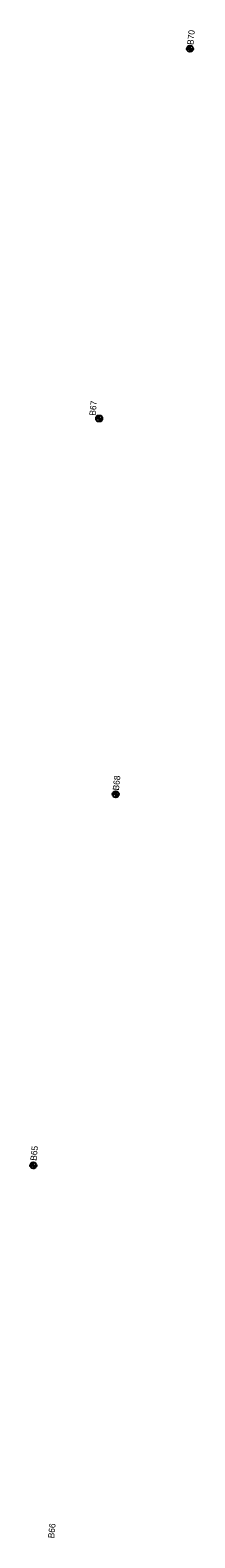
# Model space of a CAD drawing. Extents: x 327762 to 372792, y 127949 to 259367.
# Drawn here: x 359410 to 359673, y 165871 to 168282 of the extents above; entities that cross this region are included whole.
import ezdxf

# ---------------------------------------------------------------- set-up
doc = ezdxf.new("R2010")
doc.units = 0
for name, color, linetype in [('E_SOIL_BORE1 [KAPUR_CADDS_LEVELS]', 7, 'Continuous'), ('E_SOIL_BORE2 [KAPUR_CADDS_LEVELS]', 7, 'Continuous'), ('P_MARK', 7, 'Continuous')]:
    doc.layers.add(name, color=color, linetype=linetype)

msp = doc.modelspace()

# ---------------------------------------------------------------- linework, layer by layer
at = {"layer": 'P_MARK'}
for p, q in [((359660.4, 168252.8), (359670.4, 168252.8)), ((359665.4, 168257.8), (359665.4, 168247.8)), ((359515.3, 167661.3), (359525.3, 167661.3)), ((359520.3, 167666.3), (359520.3, 167656.3)), ((359541.8, 167060.1), (359551.8, 167060.1)), ((359546.8, 167065.1), (359546.8, 167055.1)), ((359410, 166466.5), (359420, 166466.5)), ((359415, 166471.5), (359415, 166461.5))]:
    msp.add_line(p, q, dxfattribs=at)
for centre in [(359665.4, 168252.8), (359520.3, 167661.3), (359546.8, 167060.1), (359415, 166466.5)]:
    msp.add_circle(centre, 5, dxfattribs=at)
for centre, radius, start, end in [((359665.4, 168252.8), 4.5, 89.9869, 179.9869), ((359665.4, 168252.8), 4, 89.9869, 179.9869), ((359665.4, 168252.8), 3.5, 89.9869, 179.9869), ((359665.4, 168252.8), 3, 89.9869, 179.9869), ((359665.4, 168252.8), 2.5, 89.9869, 179.9869), ((359665.4, 168252.8), 2, 89.9869, 179.9869), ((359665.4, 168252.8), 1.5, 89.9869, 179.9869), ((359665.4, 168252.8), 1, 89.9869, 179.9869), ((359665.4, 168252.8), 0.5, 89.9869, 179.9869), ((359665.4, 168252.8), 4.5, 269.9869, 359.9869), ((359665.4, 168252.8), 4, 269.9869, 359.9869), ((359665.4, 168252.8), 3.5, 269.9869, 359.9869), ((359665.4, 168252.8), 3, 269.9869, 359.9869), ((359665.4, 168252.8), 2.5, 269.9869, 359.9869), ((359665.4, 168252.8), 2, 269.9869, 359.9869), ((359665.4, 168252.8), 1.5, 269.9869, 359.9869), ((359665.4, 168252.8), 1, 269.9869, 359.9869), ((359665.4, 168252.8), 0.5, 269.9869, 359.9869), ((359520.3, 167661.3), 4.5, 89.9869, 179.9869), ((359520.3, 167661.3), 4, 89.9869, 179.9869), ((359520.3, 167661.3), 3.5, 89.9869, 179.9869), ((359520.3, 167661.3), 3, 89.9869, 179.9869), ((359520.3, 167661.3), 2.5, 89.9869, 179.9869), ((359520.3, 167661.3), 2, 89.9869, 179.9869), ((359520.3, 167661.3), 1.5, 89.9869, 179.9869), ((359520.3, 167661.3), 1, 89.9869, 179.9869), ((359520.3, 167661.3), 0.5, 89.9869, 179.9869), ((359520.3, 167661.3), 4.5, 269.9869, 359.9869), ((359520.3, 167661.3), 4, 269.9869, 359.9869), ((359520.3, 167661.3), 3.5, 269.9869, 359.9869), ((359520.3, 167661.3), 3, 269.9869, 359.9869), ((359520.3, 167661.3), 2.5, 269.9869, 359.9869), ((359520.3, 167661.3), 2, 269.9869, 359.9869), ((359520.3, 167661.3), 1.5, 269.9869, 359.9869), ((359520.3, 167661.3), 1, 269.9869, 359.9869), ((359520.3, 167661.3), 0.5, 269.9869, 359.9869), ((359546.8, 167060.1), 4.5, 89.9869, 179.9869), ((359546.8, 167060.1), 4, 89.9869, 179.9869), ((359546.8, 167060.1), 3.5, 89.9869, 179.9869), ((359546.8, 167060.1), 3, 89.9869, 179.9869), ((359546.8, 167060.1), 2.5, 89.9869, 179.9869), ((359546.8, 167060.1), 2, 89.9869, 179.9869), ((359546.8, 167060.1), 1.5, 89.9869, 179.9869), ((359546.8, 167060.1), 1, 89.9869, 179.9869), ((359546.8, 167060.1), 0.5, 89.9869, 179.9869), ((359546.8, 167060.1), 4.5, 269.9869, 359.9869), ((359546.8, 167060.1), 4, 269.9869, 359.9869), ((359546.8, 167060.1), 3.5, 269.9869, 359.9869), ((359546.8, 167060.1), 3, 269.9869, 359.9869), ((359546.8, 167060.1), 2.5, 269.9869, 359.9869), ((359546.8, 167060.1), 2, 269.9869, 359.9869), ((359546.8, 167060.1), 1.5, 269.9869, 359.9869), ((359546.8, 167060.1), 1, 269.9869, 359.9869), ((359546.8, 167060.1), 0.5, 269.9869, 359.9869), ((359415, 166466.5), 4.5, 89.9869, 179.9869), ((359415, 166466.5), 4, 89.9869, 179.9869), ((359415, 166466.5), 3.5, 89.9869, 179.9869), ((359415, 166466.5), 3, 89.9869, 179.9869), ((359415, 166466.5), 2.5, 89.9869, 179.9869), ((359415, 166466.5), 2, 89.9869, 179.9869), ((359415, 166466.5), 1.5, 89.9869, 179.9869), ((359415, 166466.5), 1, 89.9869, 179.9869), ((359415, 166466.5), 0.5, 89.9869, 179.9869), ((359415, 166466.5), 4.5, 269.9869, 359.9869), ((359415, 166466.5), 4, 269.9869, 359.9869), ((359415, 166466.5), 3.5, 269.9869, 359.9869), ((359415, 166466.5), 3, 269.9869, 359.9869), ((359415, 166466.5), 2.5, 269.9869, 359.9869), ((359415, 166466.5), 2, 269.9869, 359.9869), ((359415, 166466.5), 1.5, 269.9869, 359.9869), ((359415, 166466.5), 1, 269.9869, 359.9869), ((359415, 166466.5), 0.5, 269.9869, 359.9869)]:
    msp.add_arc(centre, radius, start, end, dxfattribs=at)

# ---------------------------------------------------------------- texts
at = {"layer": 'E_SOIL_BORE1 [KAPUR_CADDS_LEVELS]'}
for s, p in [('B70', (359670.8, 168258.5)), ('B67', (359514.4, 167665.5)), ('B68', (359551.8, 167065.9))]:
    msp.add_text(s, height=10, rotation=84.1728, dxfattribs=at).set_placement(p)
at = {"layer": 'E_SOIL_BORE2 [KAPUR_CADDS_LEVELS]'}
for s, p in [('B65', (359420.1, 166473.6)), ('B66', (359448.3, 165869.7))]:
    msp.add_text(s, height=10, rotation=84.1728, dxfattribs=at).set_placement(p)

doc.saveas('drawing.dxf')
